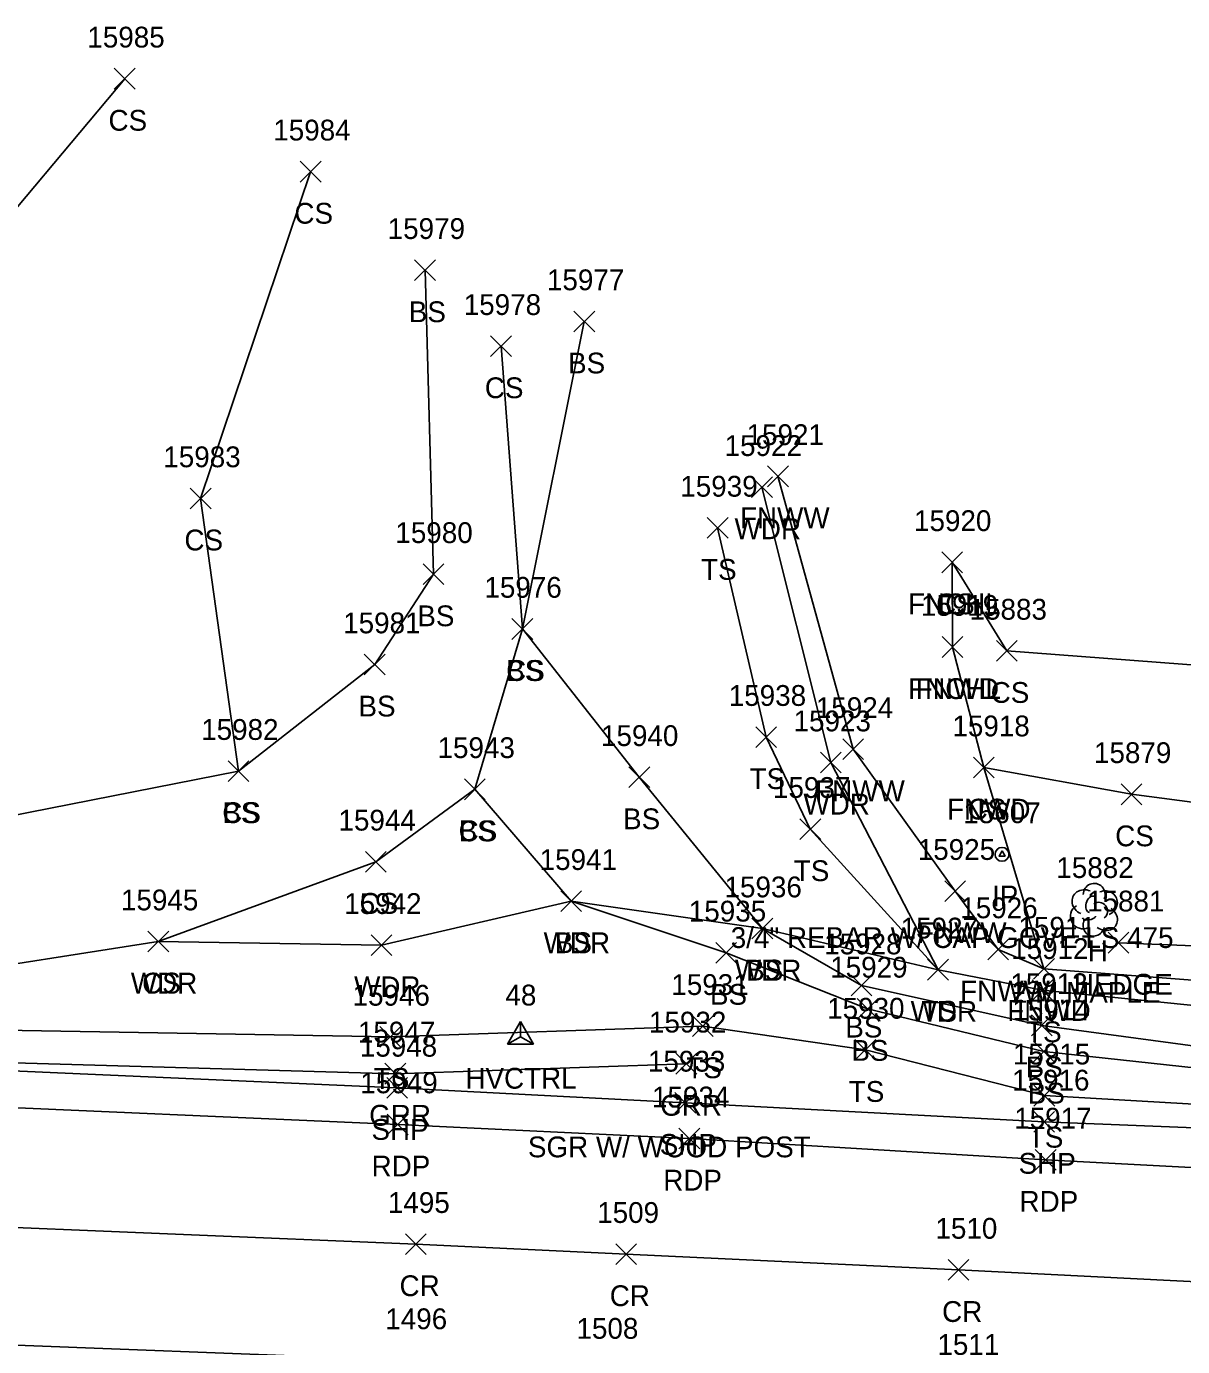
# Model space of a CAD drawing. Extents: x 1606530 to 1613020, y 784959 to 789666.
# Drawn here: x 1609388.2 to 1609499.3, y 788433.6 to 788560.5 of the extents above; entities that cross this region are included whole.
import ezdxf

# ---------------------------------------------------------------- set-up
doc = ezdxf.new("R2010")
doc.units = 0
for name, color, linetype in [('C_A', 7, 'Continuous'), ('C_I', 7, 'Continuous'), ('CPSM', 7, 'Continuous'), ('L_A', 7, 'Continuous'), ('L_C', 7, 'Continuous'), ('L_I', 7, 'Continuous'), ('L_TIC', 7, 'Continuous'), ('LAHR', 7, 'Continuous'), ('LAWA', 7, 'Continuous'), ('LELB', 7, 'Continuous'), ('LFNC', 7, 'Continuous'), ('LTD', 7, 'Continuous'), ('M_A', 7, 'Continuous'), ('M_C', 7, 'Continuous'), ('M_I', 7, 'Continuous'), ('MPIR', 7, 'Continuous'), ('P_A', 7, 'Continuous'), ('P_I', 7, 'Continuous'), ('P_TIC', 7, 'Continuous'), ('PET', 7, 'Continuous'), ('PRC', 7, 'Continuous'), ('PSP', 7, 'Continuous'), ('R_A', 7, 'Continuous'), ('R_C', 7, 'Continuous'), ('R_I', 7, 'Continuous'), ('R_TIC', 7, 'Continuous'), ('RGR', 7, 'Continuous')]:
    doc.layers.add(name, color=color, linetype=linetype)

msp = doc.modelspace()

# ---------------------------------------------------------------- linework, layer by layer
at = {"layer": 'CPSM'}
for p, q in [((1609434.44, 788462.66), (1609435.69, 788464.83)), ((1609436.94, 788462.66), (1609435.69, 788464.83)), ((1609435.69, 788463.38), (1609435.69, 788464.83)), ((1609434.44, 788462.66), (1609435.69, 788463.38)), ((1609434.44, 788462.66), (1609436.94, 788462.66)), ((1609435.69, 788463.38), (1609435.69, 788463.38)), ((1609435.69, 788463.38), (1609436.94, 788462.66))]:
    msp.add_line(p, q, dxfattribs=at)
at = {"layer": 'L_TIC'}
for points in [[(1609396.63, 788554.5), (1609398.63, 788556.5)], [(1609398.63, 788554.5), (1609396.63, 788556.5)], [(1609414.5, 788545.56), (1609416.5, 788547.56)], [(1609416.5, 788545.56), (1609414.5, 788547.56)], [(1609425.5, 788536.09), (1609427.5, 788538.09)], [(1609427.5, 788536.09), (1609425.5, 788538.09)], [(1609440.81, 788531.16), (1609442.81, 788533.16)], [(1609442.81, 788531.16), (1609440.81, 788533.16)], [(1609432.81, 788528.78), (1609434.81, 788530.78)], [(1609434.81, 788528.78), (1609432.81, 788530.78)], [(1609457.89, 788515.22), (1609459.89, 788517.22)], [(1609459.89, 788515.22), (1609457.89, 788517.22)], [(1609459.43, 788516.27), (1609461.43, 788518.27)], [(1609461.43, 788516.27), (1609459.43, 788518.27)], [(1609403.93, 788514.14), (1609405.93, 788516.14)], [(1609405.93, 788514.14), (1609403.93, 788516.14)], [(1609453.63, 788511.31), (1609455.63, 788513.31)], [(1609455.63, 788511.31), (1609453.63, 788513.31)], [(1609476.18, 788508), (1609478.18, 788510)], [(1609478.18, 788508), (1609476.18, 788510)], [(1609476.18, 788508), (1609478.18, 788510)], [(1609478.18, 788508), (1609476.18, 788510)], [(1609426.32, 788506.85), (1609428.32, 788508.85)], [(1609428.32, 788506.85), (1609426.32, 788508.85)], [(1609434.86, 788501.59), (1609436.86, 788503.59)], [(1609436.86, 788501.59), (1609434.86, 788503.59)], [(1609434.86, 788501.59), (1609436.86, 788503.59)], [(1609436.86, 788501.59), (1609434.86, 788503.59)], [(1609476.21, 788499.85), (1609478.21, 788501.85)], [(1609478.21, 788499.85), (1609476.21, 788501.85)], [(1609476.21, 788499.85), (1609478.21, 788501.85)], [(1609478.21, 788499.85), (1609476.21, 788501.85)], [(1609481.44, 788499.48), (1609483.44, 788501.48)], [(1609483.44, 788499.48), (1609481.44, 788501.48)], [(1609481.44, 788499.48), (1609483.44, 788501.48)], [(1609483.44, 788499.48), (1609481.44, 788501.48)], [(1609420.66, 788498.17), (1609422.66, 788500.17)], [(1609422.66, 788498.17), (1609420.66, 788500.17)], [(1609458.29, 788491.19), (1609460.29, 788493.19)], [(1609460.29, 788491.19), (1609458.29, 788493.19)], [(1609466.66, 788490.02), (1609468.66, 788492.02)], [(1609468.66, 788490.02), (1609466.66, 788492.02)], [(1609464.52, 788488.74), (1609466.52, 788490.74)], [(1609466.52, 788488.74), (1609464.52, 788490.74)], [(1609407.57, 788487.92), (1609409.57, 788489.92)], [(1609409.57, 788487.92), (1609407.57, 788489.92)], [(1609407.57, 788487.92), (1609409.57, 788489.92)], [(1609409.57, 788487.92), (1609407.57, 788489.92)], [(1609446.1, 788487.33), (1609448.1, 788489.33)], [(1609448.1, 788487.33), (1609446.1, 788489.33)], [(1609479.22, 788488.26), (1609481.22, 788490.26)], [(1609481.22, 788488.26), (1609479.22, 788490.26)], [(1609479.22, 788488.26), (1609481.22, 788490.26)], [(1609481.22, 788488.26), (1609479.22, 788490.26)], [(1609430.29, 788486.17), (1609432.29, 788488.17)], [(1609432.29, 788486.17), (1609430.29, 788488.17)], [(1609430.29, 788486.17), (1609432.29, 788488.17)], [(1609432.29, 788486.17), (1609430.29, 788488.17)], [(1609430.29, 788486.17), (1609432.29, 788488.17)], [(1609432.29, 788486.17), (1609430.29, 788488.17)], [(1609493.41, 788485.69), (1609495.41, 788487.69)], [(1609495.41, 788485.69), (1609493.41, 788487.69)], [(1609493.41, 788485.69), (1609495.41, 788487.69)], [(1609495.41, 788485.69), (1609493.41, 788487.69)], [(1609462.54, 788482.34), (1609464.54, 788484.34)], [(1609464.54, 788482.34), (1609462.54, 788484.34)], [(1609420.77, 788479.2), (1609422.77, 788481.2)], [(1609422.77, 788479.2), (1609420.77, 788481.2)], [(1609476.46, 788476.38), (1609478.46, 788478.38)], [(1609478.46, 788476.38), (1609476.46, 788478.38)], [(1609439.54, 788475.41), (1609441.54, 788477.41)], [(1609441.54, 788475.41), (1609439.54, 788477.41)], [(1609439.54, 788475.41), (1609441.54, 788477.41)], [(1609441.54, 788475.41), (1609439.54, 788477.41)], [(1609457.93, 788472.78), (1609459.93, 788474.78)], [(1609459.93, 788472.78), (1609457.93, 788474.78)], [(1609457.93, 788472.78), (1609459.93, 788474.78)], [(1609459.93, 788472.78), (1609457.93, 788474.78)], [(1609399.86, 788471.53), (1609401.86, 788473.53)], [(1609401.86, 788471.53), (1609399.86, 788473.53)], [(1609399.86, 788471.53), (1609401.86, 788473.53)], [(1609401.86, 788471.53), (1609399.86, 788473.53)], [(1609421.32, 788471.18), (1609423.32, 788473.18)], [(1609423.32, 788471.18), (1609421.32, 788473.18)], [(1609480.6, 788470.77), (1609482.6, 788472.77)], [(1609482.6, 788470.77), (1609480.6, 788472.77)], [(1609492.17, 788471.42), (1609494.17, 788473.42)], [(1609494.17, 788471.42), (1609492.17, 788473.42)], [(1609454.45, 788470.45), (1609456.45, 788472.45)], [(1609456.45, 788470.45), (1609454.45, 788472.45)], [(1609474.82, 788468.82), (1609476.82, 788470.82)], [(1609476.82, 788468.82), (1609474.82, 788470.82)], [(1609474.82, 788468.82), (1609476.82, 788470.82)], [(1609476.82, 788468.82), (1609474.82, 788470.82)], [(1609485, 788468.9), (1609487, 788470.9)], [(1609487, 788468.9), (1609485, 788470.9)], [(1609467.46, 788467.3), (1609469.46, 788469.3)], [(1609469.46, 788467.3), (1609467.46, 788469.3)], [(1609484.87, 788466.85), (1609486.87, 788468.85)], [(1609486.87, 788466.85), (1609484.87, 788468.85)], [(1609468.05, 788465.06), (1609470.05, 788467.06)], [(1609470.05, 788465.06), (1609468.05, 788467.06)], [(1609452.21, 788463.39), (1609454.21, 788465.39)], [(1609454.21, 788463.39), (1609452.21, 788465.39)], [(1609484.8, 788463.47), (1609486.8, 788465.47)], [(1609486.8, 788463.47), (1609484.8, 788465.47)], [(1609422.17, 788462.36), (1609424.17, 788464.36)], [(1609424.17, 788462.36), (1609422.17, 788464.36)], [(1609467.83, 788461.11), (1609469.83, 788463.11)], [(1609469.83, 788461.11), (1609467.83, 788463.11)], [(1609484.99, 788460.95), (1609486.99, 788462.95)], [(1609486.99, 788460.95), (1609484.99, 788462.95)], [(1609485.04, 788456.71), (1609487.04, 788458.71)], [(1609487.04, 788456.71), (1609485.04, 788458.71)]]:
    msp.add_lwpolyline(points, dxfattribs=at)
at = {"layer": 'LAHR'}
msp.add_lwpolyline([(1609512.73, 788471.63), (1609504.39, 788471.94), (1609493.17, 788472.42)], dxfattribs=at)
at = {"layer": 'LAWA'}
msp.add_lwpolyline([(1609458.89, 788516.22), (1609465.52, 788489.74), (1609475.82, 788469.82), (1609458.93, 788473.78), (1609440.54, 788476.41), (1609422.32, 788472.18), (1609400.86, 788472.53), (1609378.74, 788469.08), (1609331.76, 788471.95), (1609305.7, 788472.62), (1609293.07, 788472.82), (1609275.81, 788471.77), (1609233.21, 788467.38), (1609185.7, 788461.65), (1609159.09, 788461.18), (1609160.3, 788482.23), (1609154.12, 788496.01), (1609177.08, 788505.79)], dxfattribs=at)
at = {"layer": 'LELB'}
for points in [[(1609397.63, 788555.5), (1609376.98, 788530.86), (1609377.49, 788492.45), (1609374.2, 788482.15)], [(1609408.57, 788488.92), (1609404.93, 788515.14), (1609415.5, 788546.56)], [(1609426.5, 788537.09), (1609427.32, 788507.85), (1609421.66, 788499.17), (1609408.57, 788488.92), (1609374.2, 788482.15), (1609350.43, 788482.46), (1609336.96, 788484.44), (1609333.39, 788484.34), (1609313.67, 788488)], [(1609573.1, 788462.74), (1609566.42, 788457.46), (1609526.94, 788458.91), (1609485.8, 788464.47), (1609468.46, 788468.3), (1609458.93, 788473.78), (1609447.1, 788488.33), (1609435.86, 788502.59), (1609441.81, 788532.16)], [(1609431.29, 788487.17), (1609435.86, 788502.59), (1609433.81, 788529.78)], [(1609572.43, 788463.82), (1609567.68, 788460.93), (1609567.68, 788460.85), (1609527.89, 788463.58), (1609485.87, 788467.85), (1609475.82, 788469.82), (1609463.54, 788483.34), (1609459.29, 788492.19), (1609454.63, 788512.31)], [(1609482.44, 788500.48), (1609477.18, 788509)], [(1609482.44, 788500.48), (1609523.4, 788497.36), (1609537.17, 788492.55), (1609551.01, 788484.2)], [(1609494.41, 788486.69), (1609480.22, 788489.26)], [(1609431.29, 788487.17), (1609421.77, 788480.2), (1609400.86, 788472.53)], [(1609571.95, 788457.09), (1609564.69, 788454.84), (1609527.27, 788457.46), (1609485.99, 788461.95), (1609469.05, 788466.06), (1609455.45, 788471.45), (1609440.54, 788476.41), (1609431.29, 788487.17)], [(1609550.35, 788477.49), (1609541.16, 788484.1), (1609517.97, 788483.58), (1609494.41, 788486.69)], [(1609570.41, 788453.62), (1609564.76, 788453.01), (1609526.4, 788455.39), (1609486.04, 788457.71), (1609468.83, 788462.11), (1609453.21, 788464.39), (1609423.17, 788463.36), (1609331.82, 788464.93), (1609285.23, 788464.87), (1609232.95, 788461.35), (1609187.32, 788454.57)]]:
    msp.add_lwpolyline(points, dxfattribs=at)
at = {"layer": 'LFNC'}
for points in [[(1609460.43, 788517.27), (1609467.66, 788491.02), (1609477.46, 788477.38), (1609481.6, 788471.77)], [(1609477.21, 788500.85), (1609477.18, 788509)], [(1609573.27, 788471.71), (1609572.43, 788463.82), (1609527.66, 788466.72), (1609486, 788469.9), (1609480.22, 788489.26), (1609477.21, 788500.85)], [(1609486, 788469.9), (1609481.6, 788471.77)]]:
    msp.add_lwpolyline(points, dxfattribs=at)
at = {"layer": 'LTD'}
msp.add_line((1609490.78, 788475.64), (1609490.78, 788475.64), dxfattribs=at)
msp.add_line((1609490.78, 788475.64), (1609490.78, 788475.64), dxfattribs=at)
msp.add_arc((1609490.83, 788477.07), 1.05, 335.5272, 180.9563, dxfattribs=at)
for centre, major_axis, ratio, start_param, end_param in [((1609489.99, 788476.31), (1.21, -0.51), 0.895232, 1.570796, 4.712389), ((1609490.58, 788476.1), (-0.208, -0.792), 0.645439, 3.141593, 6.283185), ((1609491.83, 788476.22), (-1.14, -0.48), 0.949671, 1.570796, 4.712389), ((1609489.7, 788474.93), (0.58, -1.04), 0.959034, 3.141593, 6.283185), ((1609491.28, 788475.47), (-0.5, 0.667), 0.989748, 3.141593, 6.283185), ((1609491.79, 788474.81), (-1.09, 0.79), 0.841452, 1.570796, 4.712389), ((1609490.79, 788474.14), (0.26, 1.06), 0.942809, 1.570796, 4.712389), ((1609490.33, 788474.89), (-0.625, -0.083), 0.423636, 0, 3.141593)]:
    msp.add_ellipse(centre, major_axis=major_axis, ratio=ratio, start_param=start_param, end_param=end_param, dxfattribs=at)
at = {"layer": 'MPIR'}
msp.add_lwpolyline([(1609481.97, 788481.25), (1609481.68, 788480.75), (1609482.26, 788480.75)], close=True, dxfattribs=at)
msp.add_circle((1609481.97, 788480.91), 0.667, dxfattribs=at)
at = {"layer": 'P_TIC'}
for points in [[(1609422.82, 788457.46), (1609424.82, 788459.46)], [(1609424.82, 788457.46), (1609422.82, 788459.46)], [(1609450.52, 788456.02), (1609452.52, 788458.02)], [(1609452.52, 788456.02), (1609450.52, 788458.02)], [(1609422.87, 788453.94), (1609424.87, 788455.94)], [(1609424.87, 788453.94), (1609422.87, 788455.94)], [(1609485.02, 788454.2), (1609487.02, 788456.2)], [(1609487.02, 788454.2), (1609485.02, 788456.2)], [(1609450.91, 788452.58), (1609452.91, 788454.58)], [(1609452.91, 788452.58), (1609450.91, 788454.58)], [(1609485.16, 788450.54), (1609487.16, 788452.54)], [(1609487.16, 788450.54), (1609485.16, 788452.54)], [(1609424.62, 788442.43), (1609426.62, 788444.43)], [(1609426.62, 788442.43), (1609424.62, 788444.43)], [(1609444.83, 788441.47), (1609446.83, 788443.47)], [(1609446.83, 788441.47), (1609444.83, 788443.47)], [(1609476.78, 788439.95), (1609478.78, 788441.95)], [(1609478.78, 788439.95), (1609476.78, 788441.95)]]:
    msp.add_lwpolyline(points, dxfattribs=at)
at = {"layer": 'PET'}
for points in [[(1609713.17, 788438.63), (1609680.93, 788440.45), (1609652, 788442.02), (1609625.85, 788443.73), (1609580.96, 788446.42), (1609565.08, 788447.47), (1609525.71, 788449.46), (1609486.16, 788451.54), (1609451.91, 788453.58), (1609423.87, 788454.94), (1609378.56, 788456.92), (1609332.01, 788457.67), (1609286.4, 788456.92), (1609233.03, 788453.52), (1609189.08, 788447.38), (1609175.76, 788445.19), (1609148.78, 788440), (1609127.71, 788434.8)], [(1608827.2, 788266.24), (1608867.86, 788290.54), (1608906.68, 788312.86), (1608942.68, 788332.75), (1608980.54, 788352.16), (1609023.57, 788373.22), (1609061.44, 788389.9), (1609090.8, 788401.17), (1609121.92, 788410.09), (1609165.17, 788420), (1609195.85, 788425.54), (1609240.14, 788431.13), (1609287.88, 788434.37), (1609331.48, 788435.11), (1609378.89, 788434.05), (1609425.43, 788432.25), (1609443.83, 788431.33), (1609477.32, 788429.78), (1609518.44, 788427.6), (1609569.18, 788424.68), (1609602.99, 788422.58), (1609641.45, 788420.37), (1609681.7, 788417.92), (1609727.38, 788415.53)]]:
    msp.add_lwpolyline(points, dxfattribs=at)
at = {"layer": 'PRC'}
msp.add_lwpolyline([(1608863.25, 788300.9), (1608901.81, 788322.6), (1608937.61, 788342.72), (1608976.12, 788362.76), (1609017.58, 788382.95), (1609062.58, 788402.24), (1609089.79, 788412.89), (1609118.81, 788421.44), (1609162.84, 788431.75), (1609194.15, 788437.36), (1609237.64, 788442.85), (1609286.9, 788446.16), (1609332.71, 788446.44), (1609379.39, 788445.34), (1609425.62, 788443.43), (1609445.83, 788442.47), (1609477.78, 788440.95), (1609519.76, 788438.85), (1609569.72, 788435.9), (1609601.73, 788434.31), (1609642.39, 788431.82), (1609682.03, 788429.15), (1609726.55, 788426.79)], dxfattribs=at)
at = {"layer": 'PSP'}
msp.add_lwpolyline([(1609713.92, 788443.12), (1609681.22, 788444.65), (1609658, 788445.99), (1609646.32, 788446.92), (1609626.34, 788447.99), (1609592.68, 788450.1), (1609566.9, 788451.27), (1609526.22, 788453.59), (1609486.02, 788455.2), (1609451.52, 788457.02), (1609423.82, 788458.46), (1609378.09, 788460.47), (1609331.88, 788461.68), (1609285.23, 788461.6), (1609232.6, 788457.92), (1609188.51, 788451.36), (1609172.5, 788448.52), (1609147.32, 788443.74), (1609126.97, 788439.13), (1609114.12, 788436.45)], dxfattribs=at)
at = {"layer": 'R_TIC'}
for points in [[(1609450.62, 788459.78), (1609452.62, 788461.78)], [(1609452.62, 788459.78), (1609450.62, 788461.78)], [(1609422.64, 788458.82), (1609424.64, 788460.82)], [(1609424.64, 788458.82), (1609422.64, 788460.82)]]:
    msp.add_lwpolyline(points, dxfattribs=at)
at = {"layer": 'RGR'}
msp.add_lwpolyline([(1609451.62, 788460.78), (1609423.64, 788459.82), (1609378.06, 788461.13), (1609332.06, 788462.45), (1609285.08, 788462.33), (1609232.47, 788458.7), (1609188.44, 788451.91), (1609171.83, 788449.19), (1609146.47, 788445.79), (1609126.98, 788443.62)], dxfattribs=at)

# ---------------------------------------------------------------- texts
at = {"layer": 'C_A'}
msp.add_text('HVCTRL', height=2, dxfattribs=at).set_placement((1609430.38, 788458.38))
at = {"layer": 'C_I'}
msp.add_text('48', height=2, dxfattribs=at).set_placement((1609434.23, 788466.38))
at = {"layer": 'L_A'}
for s, p in [('CS', (1609396.07, 788550.5)), ('CS', (1609413.94, 788541.56)), ('BS', (1609424.94, 788532.09)), ('BS', (1609440.25, 788527.16)), ('CS', (1609432.25, 788524.78)), ('FNWW', (1609456.78, 788512.27)), ('CS', (1609403.37, 788510.14)), ('WDR', (1609456.26, 788511.22)), ('TS', (1609453.04, 788507.31)), ('FNCHL', (1609472.93, 788504)), ('CS', (1609475.63, 788504)), ('BS', (1609425.76, 788502.85)), ('CS', (1609434.3, 788497.59)), ('BS', (1609434.3, 788497.59)), ('FNCHL', (1609472.95, 788495.85)), ('FNWD', (1609473.67, 788495.85)), ('CS', (1609480.88, 788495.48)), ('CS', (1609480.88, 788495.48)), ('BS', (1609420.1, 788494.17)), ('TS', (1609457.7, 788487.19)), ('FNWW', (1609464.01, 788486.02)), ('WDR', (1609462.88, 788484.74)), ('CS', (1609407.01, 788483.92)), ('BS', (1609407.01, 788483.92)), ('FNWD', (1609476.69, 788484.26)), ('CS', (1609478.66, 788484.26)), ('CS', (1609429.73, 788482.17)), ('CS', (1609429.73, 788482.17)), ('BS', (1609429.73, 788482.17)), ('BS', (1609445.54, 788483.33)), ('CS', (1609492.85, 788481.69)), ('CS', (1609492.85, 788481.69)), ('TS', (1609461.95, 788478.34)), ('CS', (1609420.21, 788475.2)), ('FNWW', (1609473.8, 788472.38)), ('WDR', (1609437.9, 788471.41)), ('BS', (1609438.98, 788471.41)), ('H', (1609490.22, 788470.64)), ('WDR', (1609456.29, 788468.78)), ('BS', (1609457.37, 788468.78)), ('WDR', (1609398.22, 788467.53)), ('CS', (1609399.3, 788467.53)), ('WDR', (1609419.68, 788467.18)), ('HEDGE', (1609488.87, 788467.42)), ('BS', (1609453.89, 788466.45)), ('FNWW', (1609477.95, 788466.77)), ('WDR', (1609473.18, 788464.82)), ('TS', (1609474.23, 788464.82)), ('FNWD', (1609482.47, 788464.9)), ('BS', (1609466.9, 788463.3)), ('TS', (1609484.28, 788462.85)), ('BS', (1609467.49, 788461.06)), ('TS', (1609451.62, 788459.39)), ('BS', (1609484.24, 788459.47)), ('TS', (1609421.58, 788458.36)), ('TS', (1609467.24, 788457.11)), ('BS', (1609484.44, 788456.95)), ('TS', (1609484.45, 788452.71))]:
    msp.add_text(s, height=2, dxfattribs=at).set_placement(p)
at = {"layer": 'L_C'}
msp.add_text('2 M.MAPLE', height=2, dxfattribs=at).set_placement((1609482.93, 788466.64))
at = {"layer": 'L_I'}
for s, p in [('15985', (1609394.04, 788558.5)), ('15984', (1609411.91, 788549.56)), ('15979', (1609422.91, 788540.09)), ('15977', (1609438.22, 788535.16)), ('15978', (1609430.22, 788532.78)), ('15921', (1609457.41, 788520.27)), ('15922', (1609455.3, 788519.22)), ('15983', (1609401.34, 788518.14)), ('15939', (1609451.04, 788515.31)), ('15920', (1609473.51, 788512)), ('15920', (1609473.51, 788512)), ('15980', (1609423.65, 788510.85)), ('15976', (1609432.21, 788505.59)), ('15976', (1609432.21, 788505.59)), ('15919', (1609474.17, 788503.85)), ('15919', (1609474.17, 788503.85)), ('15883', (1609478.85, 788503.48)), ('15883', (1609478.85, 788503.48)), ('15981', (1609418.63, 788502.17)), ('15938', (1609455.7, 788495.19)), ('15924', (1609464.07, 788494.02)), ('15923', (1609461.93, 788492.74)), ('15982', (1609404.98, 788491.92)), ('15982', (1609404.98, 788491.92)), ('15940', (1609443.42, 788491.33)), ('15918', (1609477.2, 788492.26)), ('15918', (1609477.2, 788492.26)), ('15943', (1609427.7, 788490.17)), ('15943', (1609427.7, 788490.17)), ('15943', (1609427.7, 788490.17)), ('15879', (1609490.81, 788489.69)), ('15879', (1609490.81, 788489.69)), ('15937', (1609459.95, 788486.34)), ('15944', (1609418.18, 788483.2)), ('15925', (1609473.87, 788480.38)), ('15941', (1609437.52, 788479.41)), ('15941', (1609437.52, 788479.41)), ('15882', (1609487.19, 788478.64)), ('15936', (1609455.29, 788476.78)), ('15936', (1609455.29, 788476.78)), ('15945', (1609397.27, 788475.53)), ('15945', (1609397.27, 788475.53)), ('15942', (1609418.73, 788475.18)), ('15926', (1609477.96, 788474.77)), ('15881', (1609490.15, 788475.42)), ('15935', (1609451.86, 788474.45)), ('15927', (1609472.23, 788472.82)), ('15927', (1609472.23, 788472.82)), ('15911', (1609483.55, 788472.9)), ('15928', (1609464.87, 788471.3)), ('15912', (1609482.85, 788470.85)), ('15929', (1609465.45, 788469.06)), ('15931', (1609450.18, 788467.39)), ('15913', (1609482.77, 788467.47)), ('15946', (1609419.53, 788466.36)), ('15930', (1609465.16, 788465.11)), ('15914', (1609482.97, 788464.95)), ('15915', (1609483.01, 788460.71))]:
    msp.add_text(s, height=2, dxfattribs=at).set_placement(p)
at = {"layer": 'M_A'}
msp.add_text('IP', height=2, dxfattribs=at).set_placement((1609481.01, 788475.91))
at = {"layer": 'M_C'}
msp.add_text('3/4" REBAR W/ CAP GOVE LS 475', height=2, dxfattribs=at).set_placement((1609455.89, 788471.91))
at = {"layer": 'M_I'}
msp.add_text('15607', height=2, dxfattribs=at).set_placement((1609478.25, 788483.91))
at = {"layer": 'P_A'}
for s, p in [('SHP', (1609421.35, 788453.46)), ('SHP', (1609449.06, 788452.02)), ('RDP', (1609421.36, 788449.94)), ('SHP', (1609483.56, 788450.2)), ('RDP', (1609449.4, 788448.58)), ('RDP', (1609483.65, 788446.54)), ('CR', (1609424.05, 788438.43)), ('CR', (1609444.26, 788437.47)), ('CR', (1609476.21, 788435.95))]:
    msp.add_text(s, height=2, dxfattribs=at).set_placement(p)
at = {"layer": 'P_I'}
for s, p in [('15948', (1609420.23, 788461.46)), ('15933', (1609447.93, 788460.02)), ('15916', (1609482.94, 788458.2)), ('15949', (1609420.28, 788457.94)), ('15934', (1609448.32, 788456.58)), ('15917', (1609483.14, 788454.54)), ('1495', (1609422.93, 788446.43)), ('1509', (1609443.05, 788445.47)), ('1510', (1609475.57, 788443.95)), ('1496', (1609422.68, 788435.25)), ('1508', (1609441.06, 788434.33)), ('1511', (1609475.76, 788432.78))]:
    msp.add_text(s, height=2, dxfattribs=at).set_placement(p)
at = {"layer": 'R_A'}
for p in [(1609449.11, 788455.78), (1609421.13, 788454.82)]:
    msp.add_text('GRR', height=2, dxfattribs=at).set_placement(p)
at = {"layer": 'R_C'}
msp.add_text('SGR W/ WOOD POST', height=2, dxfattribs=at).set_placement((1609436.39, 788451.78))
at = {"layer": 'R_I'}
for s, p in [('15932', (1609448.03, 788463.78)), ('15947', (1609420.05, 788462.82))]:
    msp.add_text(s, height=2, dxfattribs=at).set_placement(p)

doc.saveas('drawing.dxf')
